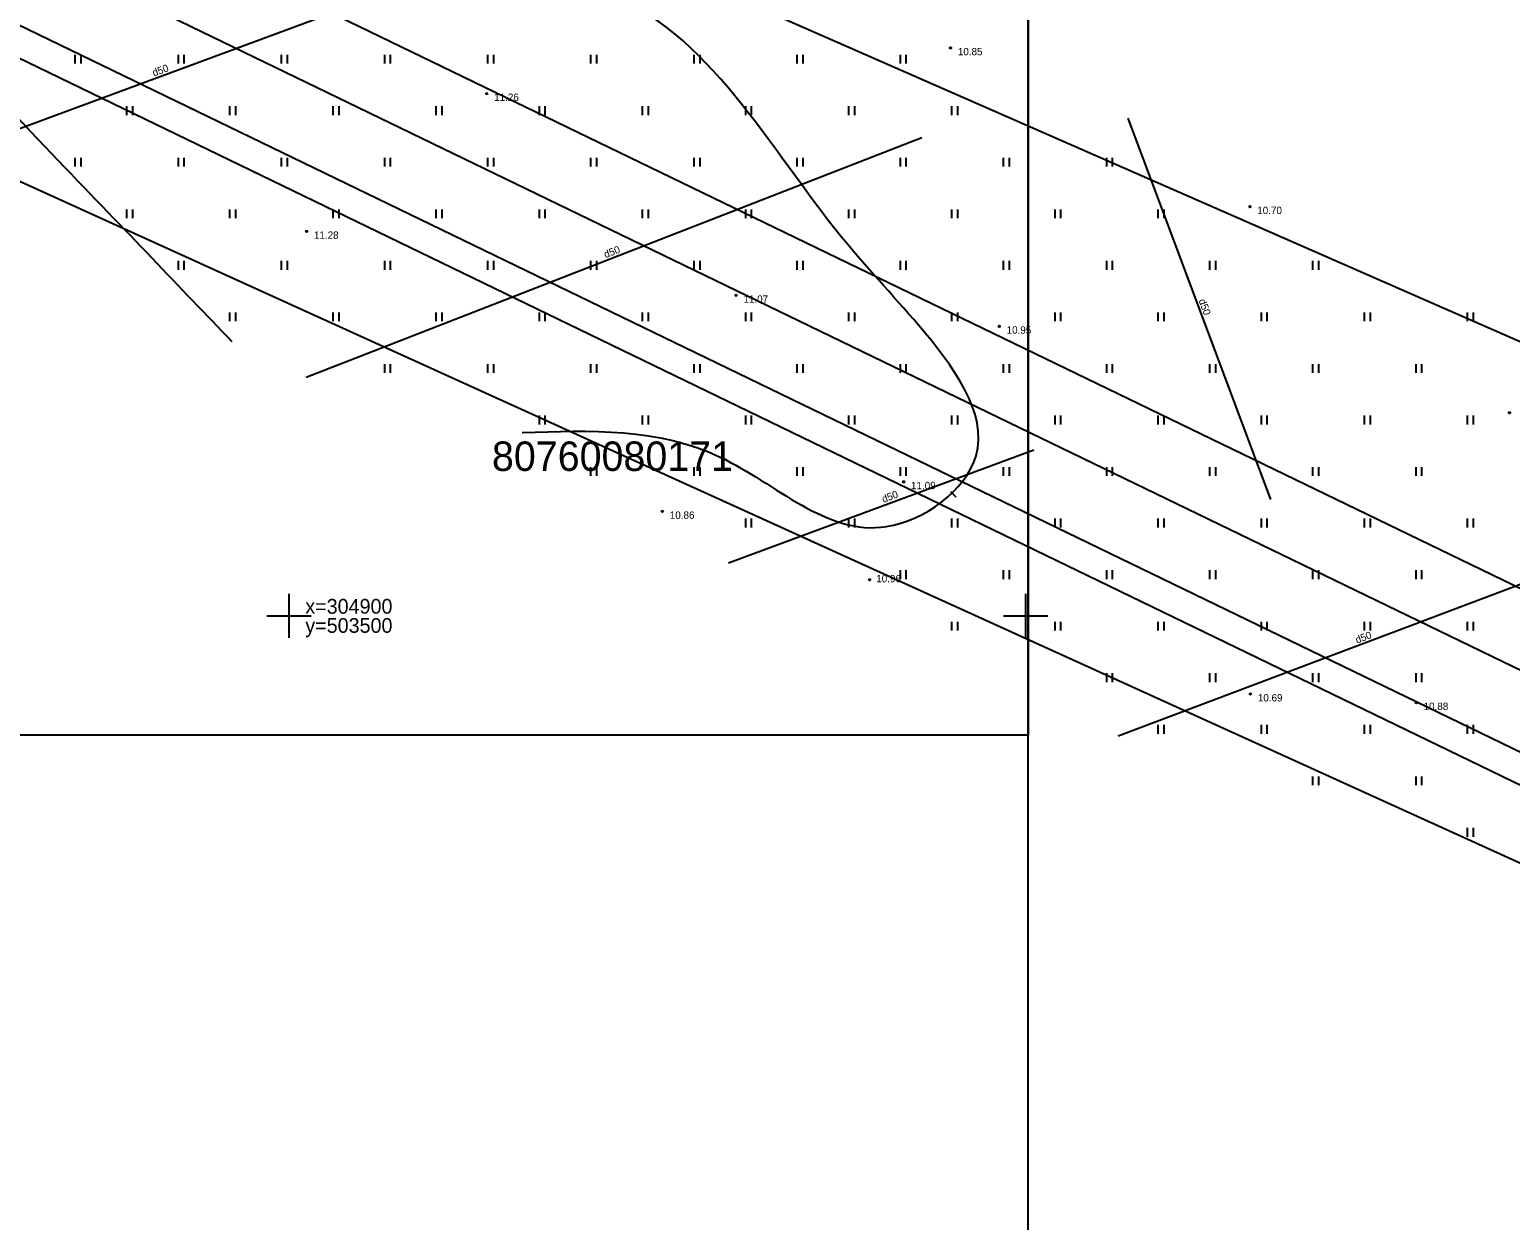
# Model space of a CAD drawing. Extents: x 503353 to 504004, y 304662 to 305049.
# Drawn here: x 503482.4 to 503582.9, y 304859 to 304939.8 of the extents above; entities that cross this region are included whole.
import ezdxf

# ---------------------------------------------------------------- set-up
doc = ezdxf.new("R2010")
doc.units = 0
for name, color, linetype in [('24', 7, 'Continuous'), ('25', 7, 'Continuous'), ('59', 7, 'Continuous'), ('APGR_ELEM_####_####_#', 7, 'Continuous'), ('DREN_VADP_####_####_#', 7, 'Continuous'), ('DREN_VADP_####_TKST_#', 7, 'Continuous'), ('GEOD_ELEM_####_####_#', 7, 'Continuous'), ('GEOD_KORD_####_TKST_#', 7, 'Continuous'), ('RAMI_PLAN_####_TKST_#', 7, 'Continuous'), ('RAMI_UZMR_####_####_#', 7, 'Continuous'), ('RELJ_AATZ_####_TKST_#', 7, 'Continuous'), ('RELJ_ELEM_####_####_#', 7, 'Continuous'), ('RELJ_HORZ_PAMT_####_#', 7, 'Continuous'), ('TERT_ELEM_####_####_#', 7, 'Continuous')]:
    doc.layers.add(name, color=color, linetype=linetype)

msp = doc.modelspace()

# ---------------------------------------------------------------- linework, layer by layer
at = {"layer": '24'}
msp.add_line((503427.05, 304966.58), (503597.27, 304884.11), dxfattribs=at)
at = {"layer": '25'}
msp.add_line((503595.59, 304890.48), (503425.18, 304973.04), dxfattribs=at)
at = {"layer": 'APGR_ELEM_####_####_#'}
for p, q in [((503412.34, 304984.81), (503586.7, 304900.35)), ((503415.95, 304969.73), (503588.68, 304886.05))]:
    msp.add_line(p, q, dxfattribs=at)
at = {"layer": 'DREN_VADP_####_####_#'}
for p, q in [((503524.01, 304948.73), (503473.44, 304930)), ((503556.93, 304933.8), (503566.63, 304907.89)), ((503501.17, 304916.21), (503542.95, 304932.47)), ((503626.09, 304918.17), (503556.29, 304891.84)), ((503529.83, 304903.61), (503550.55, 304911.28))]:
    msp.add_line(p, q, dxfattribs=at)
at = {"layer": 'GEOD_ELEM_####_####_#'}
for p, q in [((503500, 304901.5), (503500, 304900)), ((503550, 304901.5), (503550, 304900)), ((503498.5, 304900), (503500, 304900)), ((503500, 304900), (503500, 304898.5)), ((503500, 304900), (503501.5, 304900)), ((503548.5, 304900), (503550, 304900)), ((503550, 304900), (503550, 304898.5)), ((503550, 304900), (503551.5, 304900))]:
    msp.add_line(p, q, dxfattribs=at)
at = {"layer": 'RAMI_PLAN_####_TKST_#'}
for points in [[(503692.78, 305049.44), (503692.78, 304852.26), (503550.18, 304852.26), (503550.18, 305049.44)], [(503550.18, 304891.91), (503353, 304891.91), (503353, 305034.51), (503550.18, 305034.51)]]:
    msp.add_lwpolyline(points, close=True, dxfattribs=at)
at = {"layer": 'RAMI_UZMR_####_####_#'}
for points in [[(503407.22, 305023.93), (503368.78, 305020.18), (503379.43, 304977.46), (503383.45, 304957.42), (503396.87, 304960.6), (503416.96, 304959.03), (503433.7, 304951.36), (503608.79, 304871.75), (503642.72, 304858.18), (503694.65, 304834.72), (503842.28, 304765.87)], [(503825.92, 304784.83), (503697.43, 304847.71), (503608.51, 304889.84), (503606.52, 304897.2), (503679.24, 304999.94), (503684.9, 305009.76), (503666.78, 305017.94), (503656.13, 304996.39), (503644.1, 304987.6), (503600.99, 304924.26), (503587.99, 304916.67), (503422.24, 304989.37), (503408.62, 305023.5), (503368.78, 305020.18)]]:
    msp.add_lwpolyline(points, dxfattribs=at)
at = {"layer": 'RELJ_ELEM_####_####_#'}
for centre in [(503544.9, 304938.56), (503513.43, 304935.46), (503565.22, 304927.78), (503501.2, 304926.1), (503530.35, 304921.76), (503548.21, 304919.66), (503582.84, 304913.79), (503541.72, 304909.1), (503525.35, 304907.09), (503539.41, 304902.45), (503565.26, 304894.69), (503576.51, 304894.11)]:
    msp.add_circle(centre, 0.05, dxfattribs=at)
at = {"layer": 'RELJ_HORZ_PAMT_####_#'}
msp.add_line((503545.28, 304908.07), (503544.92, 304908.42), dxfattribs=at)
for points in [[(503515.84, 304912.45), (503529.27, 304910.78), (503540.55, 304906.06), (503546.64, 304910.87), (503542.75, 304919.71), (503537.5, 304925.72), (503521.56, 304942.2), (503504.79, 304943.1), (503497.96, 304945.18), (503488.51, 304949.45), (503475.43, 304946.23), (503484.34, 304930.92), (503496.13, 304918.62)], [(503653.86, 304861.22), (503644, 304865.05), (503628.51, 304872.58), (503611.97, 304878.99), (503602.44, 304884.19), (503591.37, 304889.4), (503588.29, 304891.57), (503604.35, 304917.91), (503624.78, 304937.69)]]:
    msp.add_spline(points, degree=3, dxfattribs=at)
at = {"layer": 'TERT_ELEM_####_####_#'}
for p, q in [((503485.5, 304937.5), (503485.5, 304938.1)), ((503485.9, 304937.5), (503485.9, 304938.1)), ((503492.5, 304937.5), (503492.5, 304938.1)), ((503492.9, 304937.5), (503492.9, 304938.1)), ((503499.5, 304937.5), (503499.5, 304938.1)), ((503499.9, 304937.5), (503499.9, 304938.1)), ((503506.5, 304937.5), (503506.5, 304938.1)), ((503506.9, 304937.5), (503506.9, 304938.1)), ((503513.5, 304937.5), (503513.5, 304938.1)), ((503513.9, 304937.5), (503513.9, 304938.1)), ((503520.5, 304937.5), (503520.5, 304938.1)), ((503520.9, 304937.5), (503520.9, 304938.1)), ((503527.5, 304937.5), (503527.5, 304938.1)), ((503527.9, 304937.5), (503527.9, 304938.1)), ((503534.5, 304937.5), (503534.5, 304938.1)), ((503534.9, 304937.5), (503534.9, 304938.1)), ((503541.5, 304937.5), (503541.5, 304938.1)), ((503541.9, 304937.5), (503541.9, 304938.1)), ((503489, 304934), (503489, 304934.6)), ((503489.4, 304934), (503489.4, 304934.6)), ((503496, 304934), (503496, 304934.6)), ((503496.4, 304934), (503496.4, 304934.6)), ((503503, 304934), (503503, 304934.6)), ((503503.4, 304934), (503503.4, 304934.6)), ((503510, 304934), (503510, 304934.6)), ((503510.4, 304934), (503510.4, 304934.6)), ((503517, 304934), (503517, 304934.6)), ((503517.4, 304934), (503517.4, 304934.6)), ((503524, 304934), (503524, 304934.6)), ((503524.4, 304934), (503524.4, 304934.6)), ((503531, 304934), (503531, 304934.6)), ((503531.4, 304934), (503531.4, 304934.6)), ((503538, 304934), (503538, 304934.6)), ((503538.4, 304934), (503538.4, 304934.6)), ((503545, 304934), (503545, 304934.6)), ((503545.4, 304934), (503545.4, 304934.6)), ((503485.5, 304930.5), (503485.5, 304931.1)), ((503485.9, 304930.5), (503485.9, 304931.1)), ((503492.5, 304930.5), (503492.5, 304931.1)), ((503492.9, 304930.5), (503492.9, 304931.1)), ((503499.5, 304930.5), (503499.5, 304931.1)), ((503499.9, 304930.5), (503499.9, 304931.1)), ((503506.5, 304930.5), (503506.5, 304931.1)), ((503506.9, 304930.5), (503506.9, 304931.1)), ((503513.5, 304930.5), (503513.5, 304931.1)), ((503513.9, 304930.5), (503513.9, 304931.1)), ((503520.5, 304930.5), (503520.5, 304931.1)), ((503520.9, 304930.5), (503520.9, 304931.1)), ((503527.5, 304930.5), (503527.5, 304931.1)), ((503527.9, 304930.5), (503527.9, 304931.1)), ((503534.5, 304930.5), (503534.5, 304931.1)), ((503534.9, 304930.5), (503534.9, 304931.1)), ((503541.5, 304930.5), (503541.5, 304931.1)), ((503541.9, 304930.5), (503541.9, 304931.1)), ((503548.5, 304930.5), (503548.5, 304931.1)), ((503548.9, 304930.5), (503548.9, 304931.1)), ((503555.5, 304930.5), (503555.5, 304931.1)), ((503555.9, 304930.5), (503555.9, 304931.1)), ((503489, 304927), (503489, 304927.6)), ((503489.4, 304927), (503489.4, 304927.6)), ((503496, 304927), (503496, 304927.6)), ((503496.4, 304927), (503496.4, 304927.6)), ((503503, 304927), (503503, 304927.6)), ((503503.4, 304927), (503503.4, 304927.6)), ((503510, 304927), (503510, 304927.6)), ((503510.4, 304927), (503510.4, 304927.6)), ((503517, 304927), (503517, 304927.6)), ((503517.4, 304927), (503517.4, 304927.6)), ((503524, 304927), (503524, 304927.6)), ((503524.4, 304927), (503524.4, 304927.6)), ((503531, 304927), (503531, 304927.6)), ((503531.4, 304927), (503531.4, 304927.6)), ((503538, 304927), (503538, 304927.6)), ((503538.4, 304927), (503538.4, 304927.6)), ((503545, 304927), (503545, 304927.6)), ((503545.4, 304927), (503545.4, 304927.6)), ((503552, 304927), (503552, 304927.6)), ((503552.4, 304927), (503552.4, 304927.6)), ((503559, 304927), (503559, 304927.6)), ((503559.4, 304927), (503559.4, 304927.6)), ((503492.5, 304923.5), (503492.5, 304924.1)), ((503492.9, 304923.5), (503492.9, 304924.1)), ((503499.5, 304923.5), (503499.5, 304924.1)), ((503499.9, 304923.5), (503499.9, 304924.1)), ((503506.5, 304923.5), (503506.5, 304924.1)), ((503506.9, 304923.5), (503506.9, 304924.1)), ((503513.5, 304923.5), (503513.5, 304924.1)), ((503513.9, 304923.5), (503513.9, 304924.1)), ((503520.5, 304923.5), (503520.5, 304924.1)), ((503520.9, 304923.5), (503520.9, 304924.1)), ((503527.5, 304923.5), (503527.5, 304924.1)), ((503527.9, 304923.5), (503527.9, 304924.1)), ((503534.5, 304923.5), (503534.5, 304924.1)), ((503534.9, 304923.5), (503534.9, 304924.1)), ((503541.5, 304923.5), (503541.5, 304924.1)), ((503541.9, 304923.5), (503541.9, 304924.1)), ((503548.5, 304923.5), (503548.5, 304924.1)), ((503548.9, 304923.5), (503548.9, 304924.1)), ((503555.5, 304923.5), (503555.5, 304924.1)), ((503555.9, 304923.5), (503555.9, 304924.1)), ((503562.5, 304923.5), (503562.5, 304924.1)), ((503562.9, 304923.5), (503562.9, 304924.1)), ((503569.5, 304923.5), (503569.5, 304924.1)), ((503569.9, 304923.5), (503569.9, 304924.1)), ((503496, 304920), (503496, 304920.6)), ((503496.4, 304920), (503496.4, 304920.6)), ((503503, 304920), (503503, 304920.6)), ((503503.4, 304920), (503503.4, 304920.6)), ((503510, 304920), (503510, 304920.6)), ((503510.4, 304920), (503510.4, 304920.6)), ((503517, 304920), (503517, 304920.6)), ((503517.4, 304920), (503517.4, 304920.6)), ((503524, 304920), (503524, 304920.6)), ((503524.4, 304920), (503524.4, 304920.6)), ((503531, 304920), (503531, 304920.6)), ((503531.4, 304920), (503531.4, 304920.6)), ((503538, 304920), (503538, 304920.6)), ((503538.4, 304920), (503538.4, 304920.6)), ((503545, 304920), (503545, 304920.6)), ((503545.4, 304920), (503545.4, 304920.6)), ((503552, 304920), (503552, 304920.6)), ((503552.4, 304920), (503552.4, 304920.6)), ((503559, 304920), (503559, 304920.6)), ((503559.4, 304920), (503559.4, 304920.6)), ((503566, 304920), (503566, 304920.6)), ((503566.4, 304920), (503566.4, 304920.6)), ((503573, 304920), (503573, 304920.6)), ((503573.4, 304920), (503573.4, 304920.6)), ((503580, 304920), (503580, 304920.6)), ((503580.4, 304920), (503580.4, 304920.6)), ((503506.5, 304916.5), (503506.5, 304917.1)), ((503506.9, 304916.5), (503506.9, 304917.1)), ((503513.5, 304916.5), (503513.5, 304917.1)), ((503513.9, 304916.5), (503513.9, 304917.1)), ((503520.5, 304916.5), (503520.5, 304917.1)), ((503520.9, 304916.5), (503520.9, 304917.1)), ((503527.5, 304916.5), (503527.5, 304917.1)), ((503527.9, 304916.5), (503527.9, 304917.1)), ((503534.5, 304916.5), (503534.5, 304917.1)), ((503534.9, 304916.5), (503534.9, 304917.1)), ((503541.5, 304916.5), (503541.5, 304917.1)), ((503541.9, 304916.5), (503541.9, 304917.1)), ((503548.5, 304916.5), (503548.5, 304917.1)), ((503548.9, 304916.5), (503548.9, 304917.1)), ((503555.5, 304916.5), (503555.5, 304917.1)), ((503555.9, 304916.5), (503555.9, 304917.1)), ((503562.5, 304916.5), (503562.5, 304917.1)), ((503562.9, 304916.5), (503562.9, 304917.1)), ((503569.5, 304916.5), (503569.5, 304917.1)), ((503569.9, 304916.5), (503569.9, 304917.1)), ((503576.5, 304916.5), (503576.5, 304917.1)), ((503576.9, 304916.5), (503576.9, 304917.1)), ((503517, 304913), (503517, 304913.6)), ((503517.4, 304913), (503517.4, 304913.6)), ((503524, 304913), (503524, 304913.6)), ((503524.4, 304913), (503524.4, 304913.6)), ((503531, 304913), (503531, 304913.6)), ((503531.4, 304913), (503531.4, 304913.6)), ((503538, 304913), (503538, 304913.6)), ((503538.4, 304913), (503538.4, 304913.6)), ((503545, 304913), (503545, 304913.6)), ((503545.4, 304913), (503545.4, 304913.6)), ((503552, 304913), (503552, 304913.6)), ((503552.4, 304913), (503552.4, 304913.6)), ((503559, 304913), (503559, 304913.6)), ((503559.4, 304913), (503559.4, 304913.6)), ((503566, 304913), (503566, 304913.6)), ((503566.4, 304913), (503566.4, 304913.6)), ((503573, 304913), (503573, 304913.6)), ((503573.4, 304913), (503573.4, 304913.6)), ((503580, 304913), (503580, 304913.6)), ((503580.4, 304913), (503580.4, 304913.6)), ((503520.5, 304909.5), (503520.5, 304910.1)), ((503520.9, 304909.5), (503520.9, 304910.1)), ((503527.5, 304909.5), (503527.5, 304910.1)), ((503527.9, 304909.5), (503527.9, 304910.1)), ((503534.5, 304909.5), (503534.5, 304910.1)), ((503534.9, 304909.5), (503534.9, 304910.1)), ((503541.5, 304909.5), (503541.5, 304910.1)), ((503541.9, 304909.5), (503541.9, 304910.1)), ((503548.5, 304909.5), (503548.5, 304910.1)), ((503548.9, 304909.5), (503548.9, 304910.1)), ((503555.5, 304909.5), (503555.5, 304910.1)), ((503555.9, 304909.5), (503555.9, 304910.1)), ((503562.5, 304909.5), (503562.5, 304910.1)), ((503562.9, 304909.5), (503562.9, 304910.1)), ((503569.5, 304909.5), (503569.5, 304910.1)), ((503569.9, 304909.5), (503569.9, 304910.1)), ((503576.5, 304909.5), (503576.5, 304910.1)), ((503576.9, 304909.5), (503576.9, 304910.1)), ((503531, 304906), (503531, 304906.6)), ((503531.4, 304906), (503531.4, 304906.6)), ((503538, 304906), (503538, 304906.6)), ((503538.4, 304906), (503538.4, 304906.6)), ((503545, 304906), (503545, 304906.6)), ((503545.4, 304906), (503545.4, 304906.6)), ((503552, 304906), (503552, 304906.6)), ((503552.4, 304906), (503552.4, 304906.6)), ((503559, 304906), (503559, 304906.6)), ((503559.4, 304906), (503559.4, 304906.6)), ((503566, 304906), (503566, 304906.6)), ((503566.4, 304906), (503566.4, 304906.6)), ((503573, 304906), (503573, 304906.6)), ((503573.4, 304906), (503573.4, 304906.6)), ((503580, 304906), (503580, 304906.6)), ((503580.4, 304906), (503580.4, 304906.6)), ((503541.5, 304902.5), (503541.5, 304903.1)), ((503541.9, 304902.5), (503541.9, 304903.1)), ((503548.5, 304902.5), (503548.5, 304903.1)), ((503548.9, 304902.5), (503548.9, 304903.1)), ((503555.5, 304902.5), (503555.5, 304903.1)), ((503555.9, 304902.5), (503555.9, 304903.1)), ((503562.5, 304902.5), (503562.5, 304903.1)), ((503562.9, 304902.5), (503562.9, 304903.1)), ((503569.5, 304902.5), (503569.5, 304903.1)), ((503569.9, 304902.5), (503569.9, 304903.1)), ((503576.5, 304902.5), (503576.5, 304903.1)), ((503576.9, 304902.5), (503576.9, 304903.1)), ((503545, 304899), (503545, 304899.6)), ((503545.4, 304899), (503545.4, 304899.6)), ((503552, 304899), (503552, 304899.6)), ((503552.4, 304899), (503552.4, 304899.6)), ((503559, 304899), (503559, 304899.6)), ((503559.4, 304899), (503559.4, 304899.6)), ((503566, 304899), (503566, 304899.6)), ((503566.4, 304899), (503566.4, 304899.6)), ((503573, 304899), (503573, 304899.6)), ((503573.4, 304899), (503573.4, 304899.6)), ((503580, 304899), (503580, 304899.6)), ((503580.4, 304899), (503580.4, 304899.6)), ((503555.5, 304895.5), (503555.5, 304896.1)), ((503555.9, 304895.5), (503555.9, 304896.1)), ((503562.5, 304895.5), (503562.5, 304896.1)), ((503562.9, 304895.5), (503562.9, 304896.1)), ((503569.5, 304895.5), (503569.5, 304896.1)), ((503569.9, 304895.5), (503569.9, 304896.1)), ((503576.5, 304895.5), (503576.5, 304896.1)), ((503576.9, 304895.5), (503576.9, 304896.1)), ((503559, 304892), (503559, 304892.6)), ((503559.4, 304892), (503559.4, 304892.6)), ((503566, 304892), (503566, 304892.6)), ((503566.4, 304892), (503566.4, 304892.6)), ((503573, 304892), (503573, 304892.6)), ((503573.4, 304892), (503573.4, 304892.6)), ((503580, 304892), (503580, 304892.6)), ((503580.4, 304892), (503580.4, 304892.6)), ((503569.5, 304888.5), (503569.5, 304889.1)), ((503569.9, 304888.5), (503569.9, 304889.1)), ((503576.5, 304888.5), (503576.5, 304889.1)), ((503576.9, 304888.5), (503576.9, 304889.1)), ((503580, 304885), (503580, 304885.6)), ((503580.4, 304885), (503580.4, 304885.6))]:
    msp.add_line(p, q, dxfattribs=at)

# ---------------------------------------------------------------- texts
at = {"layer": '59'}
msp.add_text('80760080171', height=2, dxfattribs=at).set_placement((503513.78, 304909.84))
at = {"layer": 'DREN_VADP_####_TKST_#'}
for rotation, p in [(20.3145, (503490.84, 304936.61)), (21.2727, (503521.49, 304924.28)), (290.5207, (503561.73, 304921.41)), (20.3333, (503540.35, 304907.67)), (20.6742, (503572.49, 304898.11))]:
    msp.add_text('d50', height=0.5, rotation=rotation, dxfattribs=at).set_placement(p)
at = {"layer": 'GEOD_KORD_####_TKST_#'}
for s, p in [('   x=304900', (503500, 304900.15)), ('   y=503500', (503500, 304898.85))]:
    msp.add_text(s, height=1, dxfattribs=at).set_placement(p)
at = {"layer": 'RELJ_AATZ_####_TKST_#'}
for s, p in [('10.85', (503545.4, 304938.06)), ('11.26', (503513.93, 304934.96)), ('10.70', (503565.72, 304927.28)), ('11.28', (503501.7, 304925.6)), ('11.07', (503530.85, 304921.26)), ('10.95', (503548.71, 304919.16)), ('11.09', (503542.22, 304908.6)), ('10.86', (503525.85, 304906.59)), ('10.96', (503539.86, 304902.28)), ('10.69', (503565.76, 304894.19)), ('10.88', (503577.01, 304893.61))]:
    msp.add_text(s, height=0.5, dxfattribs=at).set_placement(p)

doc.saveas('drawing.dxf')
